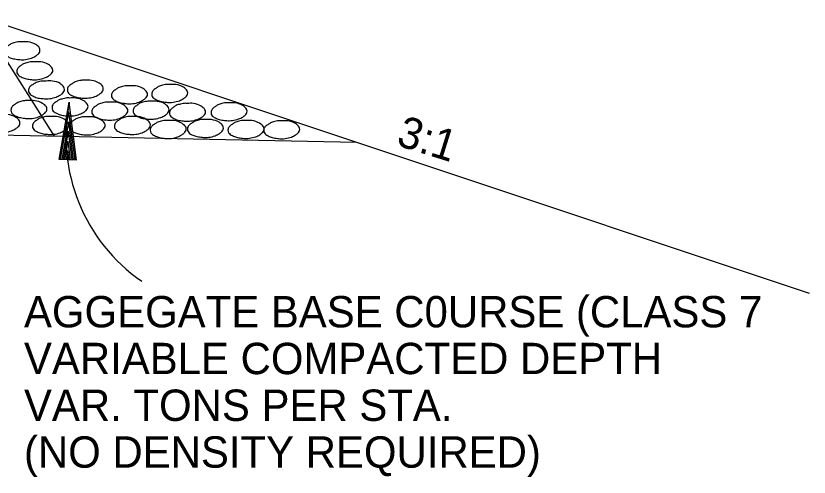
# Model space of a CAD drawing. Extents: x 714919 to 718439, y 1619644 to 1621844.
# Drawn here: x 717280.7 to 717660.4, y 1620267.6 to 1620488.2 of the extents above; entities that cross this region are included whole.
import ezdxf

# ---------------------------------------------------------------- set-up
doc = ezdxf.new("R2010")
doc.units = 0
doc.layers.add('Default', color=7, linetype='Continuous')

msp = doc.modelspace()

# ---------------------------------------------------------------- linework, layer by layer
at = {"layer": 'Default'}
for p, q in [((717262.56, 1620488.17), (717299.04, 1620430.69)), ((717262.56, 1620488.17), (717660.39, 1620355.56)), ((717301.41, 1620419.5), (717306.31, 1620446.92)), ((717309.72, 1620419.24), (717306.31, 1620446.92)), ((716665.66, 1620443.36), (717443.68, 1620427.8)), ((717302.15, 1620419.41), (717306.15, 1620442.31)), ((717309.05, 1620419.24), (717306.15, 1620442.31)), ((717302.83, 1620419.44), (717306.05, 1620437.55)), ((717308.32, 1620419.26), (717306.05, 1620437.55)), ((717303.56, 1620419.39), (717305.94, 1620432.98)), ((717307.61, 1620419.28), (717305.94, 1620432.98)), ((717304.23, 1620419.4), (717305.79, 1620428.3)), ((717306.89, 1620419.34), (717305.79, 1620428.3)), ((717304.95, 1620419.36), (717305.65, 1620423.73)), ((717306.23, 1620419.32), (717305.65, 1620423.73)), ((717309.72, 1620419.24), (717301.41, 1620419.5))]:
    msp.add_line(p, q, dxfattribs=at)
msp.add_arc((717388.95, 1620430.52), 84.25, 168.7799, 235.2689, dxfattribs=at)
for points in [[(717283.5, 1620475.77), (717286.58, 1620475.75), (717290.24, 1620474.46), (717292.04, 1620472.79), (717292.28, 1620471.7), (717291.35, 1620469.85), (717290.3, 1620469.06), (717288.29, 1620468.01), (717285.35, 1620467.33), (717283.82, 1620467.17), (717281.58, 1620467.39), (717279.04, 1620467.81), (717277.13, 1620468.56), (717275.36, 1620470.03), (717275.06, 1620471.2), (717275.58, 1620472.85), (717276.99, 1620473.91), (717278.28, 1620474.76), (717280.33, 1620475.47), (717281.6, 1620475.75), (717283.5, 1620475.77)], [(717289.62, 1620466.2), (717292.66, 1620466.16), (717296.31, 1620464.91), (717298.12, 1620463.16), (717298.44, 1620462.15), (717297.47, 1620460.26), (717296.41, 1620459.41), (717294.41, 1620458.51), (717291.43, 1620457.72), (717289.9, 1620457.6), (717287.64, 1620457.76), (717285.17, 1620458.2), (717283.25, 1620458.97), (717281.48, 1620460.4), (717281.18, 1620461.61), (717281.7, 1620463.22), (717283.09, 1620464.39), (717284.38, 1620465.25), (717286.46, 1620465.88), (717287.71, 1620466.16), (717289.62, 1620466.2)], [(717295.25, 1620457.02), (717298.23, 1620456.98), (717301.94, 1620455.79), (717303.69, 1620454.04), (717304.01, 1620453.03), (717303.07, 1620451.12), (717301.98, 1620450.31), (717299.99, 1620449.37), (717297.05, 1620448.6), (717295.48, 1620448.48), (717293.24, 1620448.64), (717290.76, 1620449.04), (717288.85, 1620449.87), (717287.04, 1620451.3), (717286.77, 1620452.45), (717287.32, 1620454.1), (717288.69, 1620455.21), (717289.96, 1620456.07), (717292.03, 1620456.78), (717293.28, 1620456.98), (717295.25, 1620457.02)], [(717313.8, 1620457.35), (717316.89, 1620457.33), (717320.55, 1620456.04), (717322.34, 1620454.37), (717322.59, 1620453.28), (717321.66, 1620451.43), (717320.61, 1620450.64), (717318.6, 1620449.6), (717315.66, 1620448.91), (717314.13, 1620448.75), (717311.89, 1620448.97), (717309.35, 1620449.39), (717307.44, 1620450.14), (717305.67, 1620451.61), (717305.37, 1620452.78), (717305.89, 1620454.43), (717307.3, 1620455.5), (717308.59, 1620456.34), (717310.64, 1620457.05), (717311.91, 1620457.33), (717313.8, 1620457.35)], [(717354.2, 1620455.35), (717357.24, 1620455.31), (717360.94, 1620454.06), (717362.7, 1620452.33), (717362.98, 1620451.32), (717362.01, 1620449.41), (717360.98, 1620448.6), (717358.97, 1620447.62), (717356.01, 1620446.87), (717354.48, 1620446.77), (717352.24, 1620446.93), (717349.75, 1620447.38), (717347.79, 1620448.16), (717346, 1620449.57), (717345.76, 1620450.74), (717346.32, 1620452.39), (717347.71, 1620453.5), (717348.96, 1620454.36), (717350.99, 1620455.07), (717352.28, 1620455.31), (717354.2, 1620455.35)], [(717334.92, 1620454.72), (717337.96, 1620454.7), (717341.63, 1620453.42), (717343.48, 1620451.68), (717343.76, 1620450.68), (717342.75, 1620448.8), (717341.71, 1620447.96), (717339.75, 1620446.97), (717336.71, 1620446.23), (717335.22, 1620446.13), (717332.95, 1620446.29), (717330.49, 1620446.73), (717328.57, 1620447.51), (717326.78, 1620448.92), (717326.5, 1620450.17), (717327.04, 1620451.74), (717328.41, 1620452.87), (717329.74, 1620453.76), (717331.72, 1620454.42), (717332.97, 1620454.7), (717334.92, 1620454.72)], [(717306.51, 1620448.88), (717309.49, 1620448.86), (717313.19, 1620447.59), (717314.95, 1620445.84), (717315.27, 1620444.84), (717314.32, 1620442.96), (717313.23, 1620442.14), (717311.24, 1620441.17), (717308.3, 1620440.4), (717306.73, 1620440.32), (717304.53, 1620440.44), (717302.02, 1620440.85), (717300.1, 1620441.67), (717298.31, 1620443.08), (717298.03, 1620444.27), (717298.59, 1620445.94), (717299.98, 1620447.07), (717301.21, 1620447.94), (717303.29, 1620448.54), (717304.57, 1620448.86), (717306.51, 1620448.88)], [(717286.77, 1620447.66), (717289.81, 1620447.62), (717293.48, 1620446.33), (717295.33, 1620444.62), (717295.62, 1620443.62), (717294.61, 1620441.72), (717293.54, 1620440.88), (717291.61, 1620439.91), (717288.57, 1620439.14), (717287.08, 1620439.06), (717284.8, 1620439.23), (717282.34, 1620439.65), (717280.43, 1620440.43), (717278.64, 1620441.86), (717278.36, 1620443.11), (717278.9, 1620444.68), (717280.27, 1620445.81), (717281.6, 1620446.68), (717283.57, 1620447.34), (717284.82, 1620447.62), (717286.77, 1620447.66)], [(717325.51, 1620446.9), (717328.55, 1620446.88), (717332.22, 1620445.59), (717334.07, 1620443.86), (717334.35, 1620442.85), (717333.35, 1620440.98), (717332.3, 1620440.13), (717330.35, 1620439.16), (717327.3, 1620438.4), (717325.83, 1620438.3), (717323.54, 1620438.46), (717321.08, 1620438.9), (717319.17, 1620439.69), (717317.38, 1620441.1), (717317.09, 1620442.35), (717317.64, 1620443.92), (717319.01, 1620445.05), (717320.34, 1620445.93), (717322.31, 1620446.6), (717323.56, 1620446.88), (717325.51, 1620446.9)], [(717345.3, 1620447.34), (717348.34, 1620447.3), (717352.05, 1620446.05), (717353.82, 1620444.28), (717354.06, 1620443.29), (717353.16, 1620441.44), (717352.09, 1620440.55), (717350.08, 1620439.6), (717347.1, 1620438.88), (717345.63, 1620438.74), (717343.33, 1620438.92), (717340.81, 1620439.32), (717338.96, 1620440.11), (717337.13, 1620441.52), (717336.86, 1620442.73), (717337.43, 1620444.38), (717338.78, 1620445.49), (717340.07, 1620446.39), (717342.1, 1620447.02), (717343.39, 1620447.3), (717345.3, 1620447.34)], [(717362.76, 1620446.31), (717365.76, 1620446.29), (717369.4, 1620445.02), (717371.24, 1620443.27), (717371.54, 1620442.3), (717370.57, 1620440.41), (717369.46, 1620439.54), (717367.49, 1620438.63), (717364.51, 1620437.91), (717363, 1620437.75), (717360.8, 1620437.93), (717358.27, 1620438.35), (717356.37, 1620439.1), (717354.54, 1620440.51), (717354.28, 1620441.74), (717354.84, 1620443.39), (717356.23, 1620444.49), (717357.48, 1620445.38), (717359.51, 1620445.97), (717360.84, 1620446.29), (717362.76, 1620446.31)], [(717382.57, 1620446.56), (717385.61, 1620446.54), (717389.31, 1620445.31), (717391.1, 1620443.56), (717391.39, 1620442.57), (717390.4, 1620440.64), (717389.33, 1620439.81), (717387.34, 1620438.9), (717384.36, 1620438.16), (717382.87, 1620438.02), (717380.59, 1620438.18), (717378.09, 1620438.6), (717376.22, 1620439.37), (717374.37, 1620440.82), (717374.15, 1620441.99), (717374.69, 1620443.62), (717376.04, 1620444.74), (717377.35, 1620445.63), (717379.36, 1620446.28), (717380.65, 1620446.54), (717382.57, 1620446.56)], [(717273.87, 1620441.02), (717276.91, 1620440.98), (717280.58, 1620439.69), (717282.43, 1620437.96), (717282.71, 1620436.95), (717281.71, 1620435.08), (717280.64, 1620434.24), (717278.7, 1620433.27), (717275.66, 1620432.5), (717274.17, 1620432.42), (717271.9, 1620432.56), (717269.44, 1620433.01), (717267.53, 1620433.79), (717265.73, 1620435.2), (717265.45, 1620436.47), (717266, 1620438.02), (717267.37, 1620439.17), (717268.7, 1620440.04), (717270.67, 1620440.7), (717271.92, 1620440.98), (717273.87, 1620441.02)], [(717297.09, 1620440.04), (717300.13, 1620440.02), (717303.8, 1620438.73), (717305.65, 1620436.99), (717305.93, 1620435.99), (717304.93, 1620434.11), (717303.86, 1620433.27), (717301.93, 1620432.28), (717298.88, 1620431.54), (717297.39, 1620431.44), (717295.12, 1620431.6), (717292.66, 1620432.04), (717290.75, 1620432.83), (717288.96, 1620434.24), (717288.67, 1620435.48), (717289.22, 1620437.06), (717290.59, 1620438.18), (717291.92, 1620439.07), (717293.89, 1620439.73), (717295.14, 1620440.02), (717297.09, 1620440.04)], [(717314.65, 1620439.86), (717317.69, 1620439.82), (717321.35, 1620438.53), (717323.21, 1620436.8), (717323.49, 1620435.79), (717322.48, 1620433.92), (717321.41, 1620433.07), (717319.48, 1620432.11), (717316.42, 1620431.34), (717314.95, 1620431.26), (717312.65, 1620431.4), (717310.22, 1620431.85), (717308.3, 1620432.63), (717306.51, 1620434.04), (717306.23, 1620435.31), (717306.77, 1620436.86), (717308.14, 1620438.01), (717309.47, 1620438.87), (717311.44, 1620439.54), (717312.69, 1620439.82), (717314.65, 1620439.86)], [(717336.28, 1620440.04), (717339.33, 1620440.02), (717343.01, 1620438.73), (717344.86, 1620436.99), (717345.15, 1620435.99), (717344.14, 1620434.11), (717343.07, 1620433.27), (717341.12, 1620432.28), (717338.08, 1620431.54), (717336.61, 1620431.44), (717334.31, 1620431.6), (717331.85, 1620432.04), (717329.94, 1620432.83), (717328.17, 1620434.24), (717327.89, 1620435.48), (717328.41, 1620437.06), (717329.8, 1620438.18), (717331.11, 1620439.07), (717333.08, 1620439.73), (717334.35, 1620440.02), (717336.28, 1620440.04)], [(717353.45, 1620438.1), (717356.49, 1620438.08), (717360.17, 1620436.79), (717362.01, 1620435.06), (717362.29, 1620434.05), (717361.3, 1620432.18), (717360.23, 1620431.34), (717358.28, 1620430.35), (717355.24, 1620429.6), (717353.77, 1620429.5), (717351.47, 1620429.66), (717349.02, 1620430.11), (717347.1, 1620430.89), (717345.31, 1620432.3), (717345.03, 1620433.55), (717345.57, 1620435.12), (717346.94, 1620436.25), (717348.27, 1620437.14), (717350.24, 1620437.8), (717351.49, 1620438.08), (717353.45, 1620438.1)], [(717371.3, 1620438.58), (717374.34, 1620438.54), (717377.98, 1620437.29), (717379.84, 1620435.52), (717380.06, 1620434.55), (717379.13, 1620432.64), (717378.06, 1620431.83), (717376.09, 1620430.84), (717373.09, 1620430.1), (717371.58, 1620429.98), (717369.32, 1620430.2), (717366.85, 1620430.6), (717364.89, 1620431.35), (717363.14, 1620432.82), (717362.82, 1620433.99), (717363.36, 1620435.62), (717364.77, 1620436.75), (717366.06, 1620437.59), (717368.12, 1620438.26), (717369.34, 1620438.54), (717371.3, 1620438.58)], [(717390.72, 1620438.1), (717393.74, 1620438.08), (717397.4, 1620436.79), (717399.26, 1620435.1), (717399.52, 1620434.03), (717398.53, 1620432.18), (717397.44, 1620431.33), (717395.53, 1620430.33), (717392.47, 1620429.7), (717391, 1620429.48), (717388.7, 1620429.72), (717386.27, 1620430.13), (717384.37, 1620430.91), (717382.56, 1620432.3), (717382.24, 1620433.53), (717382.82, 1620435.16), (717384.19, 1620436.29), (717385.52, 1620437.13), (717387.49, 1620437.76), (717388.74, 1620438.08), (717390.72, 1620438.1)], [(717407.8, 1620437.97), (717410.88, 1620437.95), (717414.55, 1620436.66), (717416.34, 1620434.99), (717416.58, 1620433.9), (717415.66, 1620432.05), (717414.61, 1620431.26), (717412.6, 1620430.21), (717409.66, 1620429.53), (717408.13, 1620429.37), (717405.89, 1620429.59), (717403.35, 1620430.01), (717401.44, 1620430.76), (717399.67, 1620432.23), (717399.36, 1620433.4), (717399.89, 1620435.05), (717401.3, 1620436.11), (717402.59, 1620436.96), (717404.64, 1620437.67), (717405.91, 1620437.95), (717407.8, 1620437.97)]]:
    msp.add_spline(points, degree=3, dxfattribs=at)

# ---------------------------------------------------------------- texts
msp.add_text('3:1', height=15, rotation=342.7185, dxfattribs=at).set_placement((717462.26, 1620426.46))
for s, p in [('AGGEGATE BASE C0URSE (CLASS 7 ', (717284.61, 1620339.2)), ('VARIABLE COMPACTED DEPTH ', (717284.61, 1620316.83)), ('VAR. TONS PER STA. ', (717284.61, 1620294.47)), ('(NO DENSITY REQUIRED)', (717284.61, 1620272.1))]:
    msp.add_text(s, height=15, dxfattribs=at).set_placement(p)

doc.saveas('drawing.dxf')
